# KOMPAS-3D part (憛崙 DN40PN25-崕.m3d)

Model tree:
1. Объединить компоненты:1  (labels: СЕНС DN40PN25-НО)

Referenced files in D:\Савин\!СЕНСОР\3D для заказчика\!Новый перечень\СЕНС\2. СЕНС-НО\DN40\: СЕНС DN40PN25-НО.a3d
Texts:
  СЕНС DN40PN25-НО
  ООО НПП Сенсор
